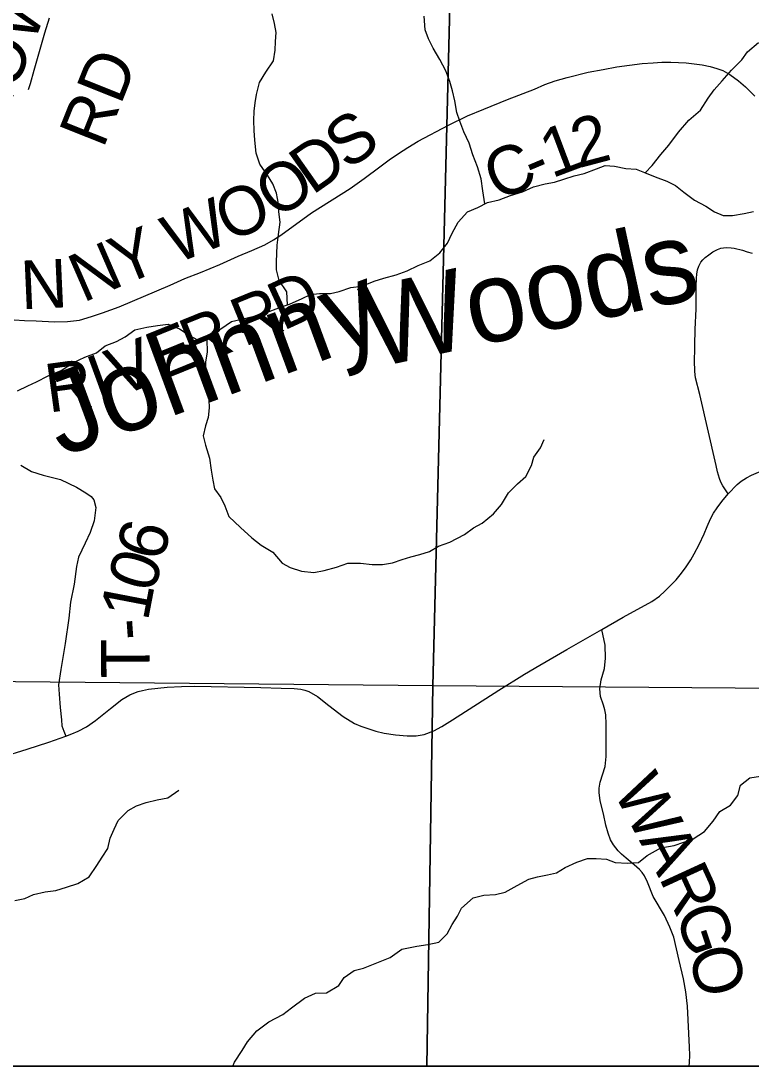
# Model space of a CAD drawing. Extents: x 0 to 34, y 0 to 22.
# Drawn here: x 5.312 to 6.166, y 14.573 to 15.796 of the extents above; entities that cross this region are included whole.
import ezdxf

# ---------------------------------------------------------------- set-up
doc = ezdxf.new("R2010")
doc.units = 0
for name, color, linetype in [('GM_X_Corporation', 7, 'Continuous'), ('GM_X_County_Road', 7, 'Continuous'), ('GM_X_County_Road_Text', 7, 'Continuous'), ('GM_X_Minor_River', 7, 'Continuous'), ('GM_X_Minor_River_Text', 7, 'Continuous'), ('GM_X_Township_Road', 7, 'Continuous'), ('GM_X_Township_Road_Text', 7, 'Continuous'), ('SH_Text', 7, 'Continuous')]:
    doc.layers.add(name, color=color, linetype=linetype)

msp = doc.modelspace()

# ---------------------------------------------------------------- linework, layer by layer
at = {"layer": 'GM_X_Corporation'}
for points in [[(1.6311, 14.5734), (8.4311, 14.5734), (8.4311, 20.028)], [(3.7221, 14.5734), (8.4311, 14.5734)]]:
    msp.add_lwpolyline(points, dxfattribs=at)
for points in [[(4.7583, 16.0869), (5.7783, 16.0638), (5.82, 16.0635), (5.7937, 15.0184), (4.7356, 15.0283), (4.7361, 15.0901)], [(5.82, 16.0635), (6.7585, 16.0372), (6.8244, 16.0368), (6.804, 15.0104), (5.7937, 15.0184)], [(4.7275, 14.5734), (5.7869, 14.5734), (5.7937, 15.0184), (4.7356, 15.0283)], [(5.7869, 14.5734), (6.7958, 14.5734), (6.804, 15.0104), (5.7937, 15.0184)]]:
    msp.add_lwpolyline(points, close=True, dxfattribs=at)
at = {"layer": 'GM_X_County_Road'}
for points in [[(5.3042, 15.4465), (5.3163, 15.4458), (5.3297, 15.4453), (5.3514, 15.4442), (5.3665, 15.4446), (5.3807, 15.4461), (5.3946, 15.4503), (5.4074, 15.4547), (5.4269, 15.4618), (5.4867, 15.4869), (5.5039, 15.4947), (5.5219, 15.5019), (5.5448, 15.5113), (5.5663, 15.5208), (5.5822, 15.5276), (5.5974, 15.5342), (5.6076, 15.54), (5.6161, 15.5454), (5.6521, 15.5715), (5.6972, 15.6), (5.7134, 15.6117), (5.7318, 15.6253), (5.7429, 15.6337), (5.7536, 15.6411), (5.7647, 15.6482), (5.7768, 15.6556), (5.8121, 15.6743), (5.8343, 15.6851), (5.8533, 15.693), (5.8811, 15.7042), (5.9127, 15.7163), (5.9248, 15.7217), (5.9369, 15.7262), (5.9508, 15.7298), (5.9756, 15.7362), (5.9929, 15.7395), (6.0092, 15.7423), (6.0388, 15.7463), (6.0515, 15.7472), (6.0616, 15.7478), (6.0723, 15.7478), (6.09, 15.7471), (6.109, 15.7447), (6.1183, 15.7428), (6.1261, 15.7407), (6.1329, 15.7381), (6.1413, 15.7335), (6.1515, 15.7259), (6.1595, 15.7191), (6.1705, 15.7081)], [(6.1393, 15.2431), (6.133, 15.2522), (6.1308, 15.2565), (6.1293, 15.2609), (6.1269, 15.2687), (6.1252, 15.2761), (6.1063, 15.3591), (6.1011, 15.3785), (6.1006, 15.3821), (6.1003, 15.3863), (6.1001, 15.3899), (6.0999, 15.3951), (6.1002, 15.4159), (6.1008, 15.436), (6.1011, 15.4424), (6.1016, 15.452), (6.1018, 15.4584), (6.1019, 15.4726), (6.102, 15.4854), (6.1022, 15.4951), (6.1026, 15.5), (6.1034, 15.5048), (6.105, 15.5093), (6.1075, 15.5141), (6.1096, 15.5167), (6.1124, 15.5193), (6.1166, 15.5227), (6.1215, 15.526), (6.1267, 15.5287), (6.1309, 15.5302), (6.1368, 15.5312), (6.1426, 15.5308), (6.1463, 15.5302), (6.1562, 15.5278), (6.1617, 15.5261), (6.1673, 15.5246)], [(6.1393, 15.2431), (6.1497, 15.2539), (6.1545, 15.2577), (6.1609, 15.2617), (6.1664, 15.2647), (6.1719, 15.2672), (6.1834, 15.2718), (6.1961, 15.2771), (6.2143, 15.2856), (6.2277, 15.2917), (6.2354, 15.2947), (6.2423, 15.2962), (6.2517, 15.2966), (6.2751, 15.2933), (6.2935, 15.29)], [(5.9917, 15.0842), (6.0166, 15.0987), (6.0501, 15.1168), (6.0588, 15.1231), (6.0653, 15.1289), (6.0786, 15.1424), (6.0848, 15.1499), (6.0903, 15.1574), (6.0956, 15.1655), (6.0997, 15.1727), (6.1054, 15.1838), (6.1111, 15.1963), (6.1149, 15.2046), (6.1187, 15.2135), (6.1222, 15.2203), (6.1265, 15.2267), (6.1319, 15.2341), (6.1393, 15.2431)], [(5.2893, 14.9349), (5.3194, 14.944), (5.3447, 14.9523), (5.3646, 14.9595), (5.3715, 14.9622), (5.3791, 14.9653), (5.3886, 14.9705), (5.3993, 14.9777), (5.4168, 14.9917), (5.43, 15.0024), (5.4394, 15.0079), (5.4441, 15.0098), (5.449, 15.0116), (5.4544, 15.013), (5.4611, 15.0142), (5.4831, 15.0166), (5.4997, 15.0176), (5.5152, 15.018), (5.5926, 15.0164), (5.6164, 15.0156), (5.6316, 15.0153), (5.6393, 15.0145), (5.6443, 15.0133), (5.6489, 15.0118), (5.6591, 15.0059), (5.6723, 14.9953), (5.6889, 14.9823), (5.7022, 14.9744), (5.7098, 14.9709), (5.719, 14.9678), (5.7271, 14.9651), (5.737, 14.9628), (5.75, 14.9611), (5.7637, 14.9598), (5.7743, 14.9599), (5.7835, 14.9612), (5.7949, 14.9655), (5.8044, 14.9707), (5.817, 14.9784), (5.8711, 15.0134), (5.9009, 15.0318), (5.919, 15.0424), (5.9505, 15.0606), (5.9917, 15.0842)], [(6.0936, 14.5734), (6.0941, 14.5775), (6.0945, 14.5862), (6.0941, 14.5956), (6.0919, 14.6435), (6.0896, 14.6603), (6.0869, 14.6756), (6.0819, 14.6969), (6.0757, 14.7242), (6.0712, 14.736), (6.0648, 14.7495), (6.0517, 14.772), (6.0449, 14.7887), (6.0413, 14.796), (6.0386, 14.7997), (6.0357, 14.8034), (6.0295, 14.8088), (6.0199, 14.8168), (6.0144, 14.8213), (6.0106, 14.8252), (6.0052, 14.8322), (6.0018, 14.8382), (5.9989, 14.8459), (5.9962, 14.8552), (5.9933, 14.8684), (5.9894, 14.8838), (5.9882, 14.8936), (5.9884, 14.8987), (5.9897, 14.9057), (5.9953, 14.924), (5.9965, 14.9356), (5.9966, 14.948), (5.9966, 14.9734), (5.996, 14.9842), (5.995, 14.9902), (5.9935, 14.9955), (5.99, 15.0059), (5.9892, 15.0147), (5.9906, 15.0252), (5.9947, 15.0384), (5.9958, 15.0507), (5.9955, 15.0658), (5.9917, 15.0842)]]:
    msp.add_lwpolyline(points, dxfattribs=at)
at = {"layer": 'GM_X_Minor_River'}
for points in [[(5.6239, 15.464), (5.6231, 15.4792), (5.614, 15.4924), (5.6109, 15.5049), (5.6109, 15.5144), (5.6113, 15.5239), (5.6116, 15.5337), (5.6135, 15.5463), (5.6153, 15.5607), (5.6138, 15.5728), (5.6134, 15.5823), (5.6111, 15.5948), (5.6065, 15.6054), (5.6004, 15.6156), (5.5916, 15.6285), (5.5871, 15.6413), (5.5855, 15.6565), (5.5847, 15.6679), (5.5843, 15.6796), (5.585, 15.6906), (5.5861, 15.7005), (5.5876, 15.7103), (5.591, 15.724), (5.5985, 15.7362), (5.6076, 15.7495), (5.6094, 15.762), (5.6098, 15.7722), (5.6105, 15.7825), (5.6086, 15.7931), (5.6059, 15.8044)], [(5.8546, 15.5822), (5.8522, 15.5975), (5.8503, 15.6115), (5.8461, 15.6256), (5.8407, 15.6396), (5.8362, 15.6532), (5.8301, 15.6665), (5.8255, 15.6789), (5.822, 15.6892), (5.8194, 15.7028), (5.8167, 15.7142), (5.8136, 15.7252), (5.809, 15.7377), (5.8022, 15.7509), (5.7942, 15.7645), (5.7888, 15.7751), (5.785, 15.7857), (5.7835, 15.8016)], [(6.0423, 15.6183), (6.0502, 15.627), (6.0604, 15.64), (6.0698, 15.651), (6.0811, 15.6662), (6.0932, 15.6799), (6.1068, 15.6917), (6.1158, 15.7058), (6.123, 15.7156), (6.1324, 15.7259), (6.143, 15.7385), (6.1554, 15.7506), (6.1618, 15.7601), (6.1747, 15.7708)], [(5.3081, 15.3636), (5.3202, 15.3693), (5.3304, 15.3739), (5.344, 15.3811), (5.3591, 15.3873), (5.3735, 15.3964), (5.3867, 15.4029), (5.4003, 15.4079), (5.4105, 15.4159), (5.4238, 15.4212), (5.434, 15.4266), (5.4453, 15.4346), (5.4593, 15.438), (5.4718, 15.44), (5.4843, 15.4415), (5.4976, 15.4359), (5.5101, 15.4276), (5.523, 15.4208), (5.537, 15.4258), (5.5457, 15.4361), (5.5585, 15.4445), (5.5702, 15.4471), (5.585, 15.4506), (5.5994, 15.4552), (5.6137, 15.4606), (5.6262, 15.4648), (5.641, 15.4713), (5.6508, 15.4762), (5.6614, 15.4774), (5.6743, 15.4771), (5.6841, 15.4798), (5.6981, 15.4844), (5.7106, 15.4859), (5.7253, 15.4917), (5.7367, 15.4951), (5.7511, 15.499), (5.7639, 15.5039), (5.7768, 15.5101), (5.7904, 15.5154), (5.8021, 15.5249), (5.8111, 15.536), (5.8164, 15.5477), (5.8236, 15.5606), (5.8345, 15.5728), (5.8466, 15.5778), (5.8576, 15.5839), (5.8716, 15.587), (5.8848, 15.592), (5.8988, 15.5962), (5.9117, 15.6019), (5.9253, 15.6057), (5.9363, 15.6077), (5.9472, 15.6111), (5.959, 15.615), (5.9707, 15.6177), (5.9851, 15.623), (5.9956, 15.6272), (6.0062, 15.6261), (6.0195, 15.6235), (6.0316, 15.6228), (6.0415, 15.6187), (6.054, 15.6138), (6.0676, 15.6089), (6.0775, 15.6036), (6.0874, 15.5957), (6.0999, 15.5863), (6.1132, 15.5795), (6.1234, 15.5727), (6.1336, 15.5686), (6.1442, 15.5686), (6.1579, 15.5709), (6.1688, 15.5732)], [(5.5294, 15.4231), (5.5298, 15.4091), (5.528, 15.3969), (5.528, 15.3867), (5.5299, 15.375), (5.5311, 15.3632), (5.5319, 15.353), (5.5323, 15.3435), (5.5312, 15.3321), (5.5278, 15.3223), (5.5252, 15.3109), (5.5279, 15.2999), (5.5325, 15.2847), (5.5344, 15.2707), (5.5363, 15.259), (5.5386, 15.2487), (5.5459, 15.2385), (5.5504, 15.2287), (5.5554, 15.2162), (5.5687, 15.2037), (5.582, 15.1916), (5.593, 15.1829), (5.6066, 15.1746), (5.6177, 15.1618), (5.6271, 15.1569), (5.6404, 15.1524), (5.6548, 15.1509), (5.6669, 15.1532), (5.6813, 15.1571), (5.6945, 15.1617), (5.7093, 15.1617), (5.7229, 15.1603), (5.735, 15.1603), (5.7468, 15.1622), (5.7581, 15.1661), (5.768, 15.1691), (5.7786, 15.1718), (5.7899, 15.1753), (5.8005, 15.1818), (5.8137, 15.1864), (5.8307, 15.1955), (5.8413, 15.2031), (5.8515, 15.2085), (5.8647, 15.2195), (5.8742, 15.2306), (5.8825, 15.2442), (5.893, 15.2545), (5.9028, 15.2633), (5.9092, 15.2762), (5.9119, 15.2857), (5.9198, 15.2967), (5.9239, 15.3066)], [(5.997, 14.8154), (6.0072, 14.8116), (6.0216, 14.8109), (6.0345, 14.8117), (6.0447, 14.8197), (6.0605, 14.8289), (6.0761, 14.8316), (6.0874, 14.8354), (6.0984, 14.8392), (6.1116, 14.848), (6.1218, 14.8598), (6.1297, 14.8712), (6.1422, 14.8785), (6.1505, 14.8899), (6.1538, 14.902), (6.1648, 14.9108), (6.1773, 14.9127)], [(5.305, 14.7671), (5.3167, 14.7694), (5.3269, 14.774), (5.3402, 14.7774), (5.3527, 14.779), (5.3655, 14.7828), (5.3784, 14.787), (5.392, 14.7947), (5.401, 14.808), (5.4071, 14.8179), (5.4138, 14.8281), (5.4165, 14.8399), (5.421, 14.8505), (5.4259, 14.8608), (5.4376, 14.8726), (5.4474, 14.8779), (5.4587, 14.8818), (5.4712, 14.8848), (5.4837, 14.8872), (5.4969, 14.8963)], [(5.56, 14.5734), (5.5619, 14.578), (5.5709, 14.5916), (5.577, 14.6019), (5.5879, 14.6145), (5.6019, 14.6251), (5.6185, 14.6339), (5.6287, 14.6415), (5.6438, 14.653), (5.6567, 14.6587), (5.6696, 14.6591), (5.6839, 14.6675), (5.6903, 14.677), (5.702, 14.6854), (5.7126, 14.6881), (5.7244, 14.6927), (5.744, 14.7003), (5.7576, 14.7102), (5.775, 14.7137), (5.7879, 14.7157), (5.8008, 14.7184), (5.8106, 14.7283), (5.8166, 14.7389), (5.8226, 14.7488), (5.8275, 14.7583), (5.8411, 14.7701), (5.8536, 14.7732), (5.8672, 14.774), (5.8786, 14.777), (5.8926, 14.7847), (5.9062, 14.7919), (5.9164, 14.795), (5.9281, 14.7973), (5.9383, 14.7996), (5.9485, 14.8057), (5.9622, 14.8118), (5.9746, 14.8161), (5.9849, 14.8161), (5.997, 14.8154)]]:
    msp.add_lwpolyline(points, dxfattribs=at)
at = {"layer": 'GM_X_Township_Road'}
for points in [[(5.345, 15.7995), (5.3396, 15.7819), (5.3272, 15.7381), (5.3228, 15.7227), (5.3203, 15.7155)], [(5.3119, 15.2766), (5.3245, 15.2691), (5.3382, 15.2648), (5.3583, 15.2596), (5.3771, 15.2508), (5.3881, 15.2442), (5.3943, 15.2398), (5.3973, 15.236), (5.3995, 15.2271), (5.3986, 15.2175), (5.3975, 15.2115), (5.3929, 15.1975), (5.387, 15.1852), (5.3792, 15.169), (5.3769, 15.1578), (5.3741, 15.1371), (5.3702, 15.1162), (5.3679, 15.0973), (5.3638, 15.0677), (5.3587, 15.0373), (5.356, 15.0193), (5.3567, 15.0084), (5.358, 14.9929), (5.3593, 14.9784), (5.3599, 14.9716), (5.3621, 14.9654), (5.3646, 14.9595)]]:
    msp.add_lwpolyline(points, dxfattribs=at)
at = {"layer": 'SH_Text'}
msp.add_line((8.4311, 14.5734), (1.6311, 14.5734), dxfattribs=at)

# ---------------------------------------------------------------- texts
at = {"layer": 'GM_X_County_Road_Text'}
for s, rotation, p in [('S', 35.6309, (5.6941, 15.6206)), ('2', 14.8516, (5.9642, 15.6237)), ('1', 20.662, (5.9329, 15.6118)), ('D', 35.1168, (5.6528, 15.5916)), ('C', 23.1053, (5.8691, 15.5847)), ('O', 35.1809, (5.6119, 15.5628)), ('-', 22.764, (5.9119, 15.603)), ('O', 23.4151, (5.555, 15.5367)), ('W', 22.1214, (5.4927, 15.5113)), ('Y', 22.1099, (5.4301, 15.4859)), ('N', 23.5158, (5.3846, 15.4661)), ('N', 2.5611, (5.3127, 15.4588)), ('D', 24.6667, (5.6184, 15.4331)), ('R', 22.2574, (5.5729, 15.4144)), ('R', 22.0829, (5.5132, 15.3902)), ('E', 22.0401, (5.4738, 15.3743)), ('V', 21.4418, (5.4267, 15.3558)), ('R', 7.7713, (5.3445, 15.3378)), ('I', 20.1172, (5.4034, 15.3472)), ('W', 298.0264, (6.0038, 14.8958)), ('A', 297.9011, (6.0347, 14.8377)), ('R', 294.6762, (6.0578, 14.7943)), ('G', 288.5167, (6.0767, 14.7534)), ('O', 284.2925, (6.0922, 14.707))]:
    msp.add_text(s, height=0.0568, rotation=rotation, dxfattribs=at).set_placement(p)
at = {"layer": 'GM_X_Minor_River_Text'}
for s, rotation, p in [('Woods', 12.212, (5.7246, 15.3897)), ('Johnny', 20.2643, (5.3591, 15.2856))]:
    msp.add_text(s, height=0.09469, rotation=rotation, dxfattribs=at).set_placement(p)
at = {"layer": 'GM_X_Township_Road_Text'}
for s, height, rotation, p in [('BROWN', 0.05682, 68.739, (5.2667, 15.6144)), ('RD', 0.05682, 68.289, (5.4082, 15.6458)), ('6', 0.0568, 76.0522, (5.4779, 15.1624)), ('0', 0.0568, 72.8636, (5.4666, 15.1256)), ('1', 0.0568, 79.0993, (5.4604, 15.0929)), ('-', 0.0568, 94.0121, (5.4623, 15.0735)), ('T', 0.0568, 90.3857, (5.4627, 15.0271))]:
    msp.add_text(s, height=height, rotation=rotation, dxfattribs=at).set_placement(p)

doc.saveas('drawing.dxf')
